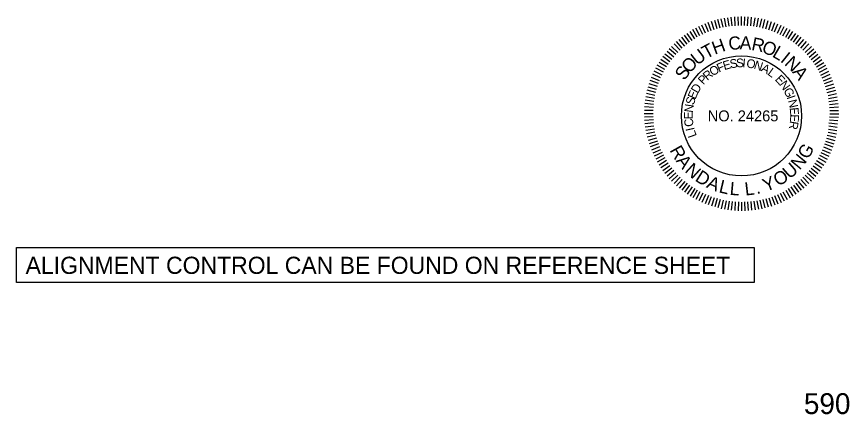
# Model space of a CAD drawing. Extents: x 1964850 to 1967424, y 1116563 to 1122204.
# Drawn here: x 1967082.7 to 1967421.9, y 1119325.5 to 1119487.7 of the extents above; entities that cross this region are included whole.
import ezdxf

# ---------------------------------------------------------------- set-up
doc = ezdxf.new("R2010")
doc.units = 0
for name, color, linetype in [('RD_DDB_Profile_Elev', 7, 'Continuous'), ('RD_Sketch1', 7, 'Continuous'), ('RD_TX_PEShield', 7, 'Continuous')]:
    doc.layers.add(name, color=color, linetype=linetype)

msp = doc.modelspace()

# ---------------------------------------------------------------- linework, layer by layer
at = {"layer": 'RD_Sketch1'}
msp.add_lwpolyline([(1967082.71, 1119393.46), (1967383.14, 1119393.46), (1967383.14, 1119379.2), (1967082.71, 1119379.2)], close=True, dxfattribs=at)
at = {"layer": 'RD_TX_PEShield'}
for p, q in [((1967364.52, 1119481.44), (1967363.18, 1119484.74)), ((1967364.52, 1119481.44), (1967363.18, 1119484.74)), ((1967365.69, 1119481.89), (1967364.47, 1119485.23)), ((1967365.69, 1119481.89), (1967364.47, 1119485.23)), ((1967366.86, 1119482.34), (1967365.76, 1119485.73)), ((1967366.86, 1119482.34), (1967365.76, 1119485.73)), ((1967368.08, 1119482.67), (1967367.1, 1119486.08)), ((1967368.08, 1119482.67), (1967367.1, 1119486.08)), ((1967369.29, 1119482.99), (1967368.43, 1119486.44)), ((1967369.29, 1119482.99), (1967368.43, 1119486.44)), ((1967370.51, 1119483.32), (1967369.77, 1119486.8)), ((1967370.51, 1119483.32), (1967369.77, 1119486.8)), ((1967371.75, 1119483.51), (1967371.13, 1119487.02)), ((1967371.75, 1119483.51), (1967371.13, 1119487.02)), ((1967372.99, 1119483.71), (1967372.5, 1119487.23)), ((1967372.99, 1119483.71), (1967372.5, 1119487.23)), ((1967374.24, 1119483.91), (1967373.86, 1119487.45)), ((1967374.24, 1119483.91), (1967373.86, 1119487.45)), ((1967375.49, 1119483.97), (1967375.24, 1119487.52)), ((1967375.49, 1119483.97), (1967375.24, 1119487.52)), ((1967376.75, 1119484.04), (1967376.62, 1119487.59)), ((1967376.75, 1119484.04), (1967376.62, 1119487.59)), ((1967378, 1119484.1), (1967378, 1119487.66)), ((1967378, 1119484.1), (1967378, 1119487.66)), ((1967379.26, 1119484.04), (1967379.38, 1119487.59)), ((1967379.26, 1119484.04), (1967379.38, 1119487.59)), ((1967380.51, 1119483.97), (1967380.76, 1119487.52)), ((1967380.51, 1119483.97), (1967380.76, 1119487.52)), ((1967381.77, 1119483.91), (1967382.14, 1119487.45)), ((1967381.77, 1119483.91), (1967382.14, 1119487.45)), ((1967383.01, 1119483.71), (1967383.51, 1119487.23)), ((1967383.01, 1119483.71), (1967383.51, 1119487.23)), ((1967384.25, 1119483.51), (1967384.87, 1119487.02)), ((1967384.25, 1119483.51), (1967384.87, 1119487.02)), ((1967385.5, 1119483.32), (1967386.24, 1119486.8)), ((1967385.5, 1119483.32), (1967386.24, 1119486.8)), ((1967385.5, 1119483.32), (1967386.24, 1119486.8)), ((1967386.71, 1119482.99), (1967387.57, 1119486.44)), ((1967386.71, 1119482.99), (1967387.57, 1119486.44)), ((1967386.71, 1119482.99), (1967387.57, 1119486.44)), ((1967387.93, 1119482.67), (1967388.91, 1119486.08)), ((1967387.93, 1119482.67), (1967388.91, 1119486.08)), ((1967387.93, 1119482.67), (1967388.91, 1119486.08)), ((1967389.14, 1119482.34), (1967390.24, 1119485.73)), ((1967389.14, 1119482.34), (1967390.24, 1119485.73)), ((1967389.14, 1119482.34), (1967390.24, 1119485.73)), ((1967390.32, 1119481.89), (1967391.53, 1119485.23)), ((1967390.32, 1119481.89), (1967391.53, 1119485.23)), ((1967390.32, 1119481.89), (1967391.53, 1119485.23)), ((1967391.49, 1119481.44), (1967392.82, 1119484.74)), ((1967391.49, 1119481.44), (1967392.82, 1119484.74)), ((1967391.49, 1119481.44), (1967392.82, 1119484.74)), ((1967358.93, 1119478.59), (1967357.04, 1119481.61)), ((1967358.93, 1119478.59), (1967357.04, 1119481.61)), ((1967359.98, 1119479.28), (1967358.2, 1119482.36)), ((1967359.98, 1119479.28), (1967358.2, 1119482.36)), ((1967361.1, 1119479.85), (1967359.43, 1119482.99)), ((1967361.1, 1119479.85), (1967359.43, 1119482.99)), ((1967362.22, 1119480.42), (1967360.66, 1119483.61)), ((1967362.22, 1119480.42), (1967360.66, 1119483.61)), ((1967363.34, 1119480.99), (1967361.89, 1119484.24)), ((1967363.34, 1119480.99), (1967361.89, 1119484.24)), ((1967392.66, 1119480.99), (1967394.11, 1119484.24)), ((1967392.66, 1119480.99), (1967394.11, 1119484.24)), ((1967392.66, 1119480.99), (1967394.11, 1119484.24)), ((1967393.79, 1119480.42), (1967395.34, 1119483.61)), ((1967393.79, 1119480.42), (1967395.34, 1119483.61)), ((1967393.79, 1119480.42), (1967395.34, 1119483.61)), ((1967394.9, 1119479.85), (1967396.57, 1119482.99)), ((1967394.9, 1119479.85), (1967396.57, 1119482.99)), ((1967394.9, 1119479.85), (1967396.57, 1119482.99)), ((1967396.03, 1119479.28), (1967397.81, 1119482.36)), ((1967396.03, 1119479.28), (1967397.81, 1119482.36)), ((1967396.03, 1119479.28), (1967397.81, 1119482.36)), ((1967397.08, 1119478.59), (1967398.97, 1119481.61)), ((1967397.08, 1119478.59), (1967398.97, 1119481.61)), ((1967397.08, 1119478.59), (1967398.97, 1119481.61)), ((1967354.86, 1119475.64), (1967352.58, 1119478.36)), ((1967354.86, 1119475.64), (1967352.58, 1119478.36)), ((1967355.84, 1119476.43), (1967353.65, 1119479.23)), ((1967355.84, 1119476.43), (1967353.65, 1119479.23)), ((1967356.82, 1119477.22), (1967354.72, 1119480.1)), ((1967356.82, 1119477.22), (1967354.72, 1119480.1)), ((1967357.87, 1119477.91), (1967355.88, 1119480.85)), ((1967357.87, 1119477.91), (1967355.88, 1119480.85)), ((1967398.13, 1119477.91), (1967400.12, 1119480.85)), ((1967398.13, 1119477.91), (1967400.12, 1119480.85)), ((1967398.13, 1119477.91), (1967400.12, 1119480.85)), ((1967399.19, 1119477.22), (1967401.28, 1119480.1)), ((1967399.19, 1119477.22), (1967401.28, 1119480.1)), ((1967399.19, 1119477.22), (1967401.28, 1119480.1)), ((1967400.17, 1119476.43), (1967402.36, 1119479.23)), ((1967400.17, 1119476.43), (1967402.36, 1119479.23)), ((1967400.17, 1119476.43), (1967402.36, 1119479.23)), ((1967401.14, 1119475.64), (1967403.43, 1119478.36)), ((1967401.14, 1119475.64), (1967403.43, 1119478.36)), ((1967401.14, 1119475.64), (1967403.43, 1119478.36)), ((1967351.22, 1119472.18), (1967348.57, 1119474.56)), ((1967351.22, 1119472.18), (1967348.57, 1119474.56)), ((1967352.11, 1119473.07), (1967349.55, 1119475.54)), ((1967352.11, 1119473.07), (1967349.55, 1119475.54)), ((1967352.99, 1119473.96), (1967350.52, 1119476.51)), ((1967352.99, 1119473.96), (1967350.52, 1119476.51)), ((1967353.88, 1119474.85), (1967351.5, 1119477.49)), ((1967353.88, 1119474.85), (1967351.5, 1119477.49)), ((1967402.12, 1119474.85), (1967404.5, 1119477.49)), ((1967402.12, 1119474.85), (1967404.5, 1119477.49)), ((1967402.12, 1119474.85), (1967404.5, 1119477.49)), ((1967403.01, 1119473.96), (1967405.48, 1119476.51)), ((1967403.01, 1119473.96), (1967405.48, 1119476.51)), ((1967403.01, 1119473.96), (1967405.48, 1119476.51)), ((1967403.9, 1119473.07), (1967406.46, 1119475.54)), ((1967403.9, 1119473.07), (1967406.46, 1119475.54)), ((1967403.9, 1119473.07), (1967406.46, 1119475.54)), ((1967404.79, 1119472.18), (1967407.44, 1119474.56)), ((1967404.79, 1119472.18), (1967407.44, 1119474.56)), ((1967404.79, 1119472.18), (1967407.44, 1119474.56)), ((1967348.84, 1119469.25), (1967345.96, 1119471.34)), ((1967348.84, 1119469.25), (1967345.96, 1119471.34)), ((1967349.63, 1119470.22), (1967346.83, 1119472.41)), ((1967349.63, 1119470.22), (1967346.83, 1119472.41)), ((1967350.42, 1119471.2), (1967347.7, 1119473.49)), ((1967350.42, 1119471.2), (1967347.7, 1119473.49)), ((1967405.58, 1119471.2), (1967408.31, 1119473.49)), ((1967405.58, 1119471.2), (1967408.31, 1119473.49)), ((1967405.58, 1119471.2), (1967408.31, 1119473.49)), ((1967406.37, 1119470.22), (1967409.17, 1119472.41)), ((1967406.37, 1119470.22), (1967409.17, 1119472.41)), ((1967406.37, 1119470.22), (1967409.17, 1119472.41)), ((1967407.16, 1119469.25), (1967410.04, 1119471.34)), ((1967407.16, 1119469.25), (1967410.04, 1119471.34)), ((1967407.16, 1119469.25), (1967410.04, 1119471.34)), ((1967346.79, 1119466.08), (1967343.7, 1119467.86)), ((1967346.79, 1119466.08), (1967343.7, 1119467.86)), ((1967347.47, 1119467.14), (1967344.46, 1119469.02)), ((1967347.47, 1119467.14), (1967344.46, 1119469.02)), ((1967348.16, 1119468.19), (1967345.21, 1119470.18)), ((1967348.16, 1119468.19), (1967345.21, 1119470.18)), ((1967407.85, 1119468.19), (1967410.8, 1119470.18)), ((1967407.85, 1119468.19), (1967410.8, 1119470.18)), ((1967407.85, 1119468.19), (1967410.8, 1119470.18)), ((1967408.53, 1119467.14), (1967411.55, 1119469.02)), ((1967408.53, 1119467.14), (1967411.55, 1119469.02)), ((1967408.53, 1119467.14), (1967411.55, 1119469.02)), ((1967409.22, 1119466.08), (1967412.3, 1119467.86)), ((1967409.22, 1119466.08), (1967412.3, 1119467.86)), ((1967409.22, 1119466.08), (1967412.3, 1119467.86)), ((1967345.65, 1119463.84), (1967342.45, 1119465.4)), ((1967345.65, 1119463.84), (1967342.45, 1119465.4)), ((1967346.22, 1119464.96), (1967343.08, 1119466.63)), ((1967346.22, 1119464.96), (1967343.08, 1119466.63)), ((1967409.79, 1119464.96), (1967412.93, 1119466.63)), ((1967409.79, 1119464.96), (1967412.93, 1119466.63)), ((1967409.79, 1119464.96), (1967412.93, 1119466.63)), ((1967410.36, 1119463.84), (1967413.56, 1119465.4)), ((1967410.36, 1119463.84), (1967413.56, 1119465.4)), ((1967410.36, 1119463.84), (1967413.56, 1119465.4)), ((1967344.17, 1119460.37), (1967340.83, 1119461.59)), ((1967344.17, 1119460.37), (1967340.83, 1119461.59)), ((1967344.62, 1119461.55), (1967341.33, 1119462.88)), ((1967344.62, 1119461.55), (1967341.33, 1119462.88)), ((1967345.07, 1119462.72), (1967341.82, 1119464.17)), ((1967345.07, 1119462.72), (1967341.82, 1119464.17)), ((1967410.93, 1119462.72), (1967414.18, 1119464.17)), ((1967410.93, 1119462.72), (1967414.18, 1119464.17)), ((1967410.93, 1119462.72), (1967414.18, 1119464.17)), ((1967411.38, 1119461.55), (1967414.68, 1119462.88)), ((1967411.38, 1119461.55), (1967414.68, 1119462.88)), ((1967411.38, 1119461.55), (1967414.68, 1119462.88)), ((1967411.83, 1119460.37), (1967415.17, 1119461.59)), ((1967411.83, 1119460.37), (1967415.17, 1119461.59)), ((1967411.83, 1119460.37), (1967415.17, 1119461.59)), ((1967343.07, 1119456.77), (1967339.62, 1119457.63)), ((1967343.07, 1119456.77), (1967339.62, 1119457.63)), ((1967343.4, 1119457.98), (1967339.98, 1119458.96)), ((1967343.4, 1119457.98), (1967339.98, 1119458.96)), ((1967343.72, 1119459.2), (1967340.34, 1119460.3)), ((1967343.72, 1119459.2), (1967340.34, 1119460.3)), ((1967412.28, 1119459.2), (1967415.67, 1119460.3)), ((1967412.28, 1119459.2), (1967415.67, 1119460.3)), ((1967412.28, 1119459.2), (1967415.67, 1119460.3)), ((1967412.61, 1119457.98), (1967416.03, 1119458.96)), ((1967412.61, 1119457.98), (1967416.03, 1119458.96)), ((1967412.61, 1119457.98), (1967416.03, 1119458.96)), ((1967412.93, 1119456.77), (1967416.38, 1119457.63)), ((1967412.93, 1119456.77), (1967416.38, 1119457.63)), ((1967412.93, 1119456.77), (1967416.38, 1119457.63)), ((1967342.55, 1119454.31), (1967339.05, 1119454.93)), ((1967342.55, 1119454.31), (1967339.05, 1119454.93)), ((1967342.75, 1119455.55), (1967339.26, 1119456.29)), ((1967342.75, 1119455.55), (1967339.26, 1119456.29)), ((1967413.26, 1119455.55), (1967416.74, 1119456.29)), ((1967413.26, 1119455.55), (1967416.74, 1119456.29)), ((1967413.26, 1119455.55), (1967416.74, 1119456.29)), ((1967413.46, 1119454.31), (1967416.96, 1119454.93)), ((1967413.46, 1119454.31), (1967416.96, 1119454.93)), ((1967413.46, 1119454.31), (1967416.96, 1119454.93)), ((1967342.09, 1119450.57), (1967338.54, 1119450.82)), ((1967342.09, 1119450.57), (1967338.54, 1119450.82)), ((1967342.16, 1119451.83), (1967338.62, 1119452.2)), ((1967342.16, 1119451.83), (1967338.62, 1119452.2)), ((1967342.35, 1119453.07), (1967338.83, 1119453.56)), ((1967342.35, 1119453.07), (1967338.83, 1119453.56)), ((1967413.65, 1119453.07), (1967417.17, 1119453.56)), ((1967413.65, 1119453.07), (1967417.17, 1119453.56)), ((1967413.65, 1119453.07), (1967417.17, 1119453.56)), ((1967413.85, 1119451.83), (1967417.39, 1119452.2)), ((1967413.85, 1119451.83), (1967417.39, 1119452.2)), ((1967413.85, 1119451.83), (1967417.39, 1119452.2)), ((1967413.92, 1119450.57), (1967417.46, 1119450.82)), ((1967413.92, 1119450.57), (1967417.46, 1119450.82)), ((1967413.92, 1119450.57), (1967417.46, 1119450.82)), ((1967341.96, 1119448.06), (1967338.4, 1119448.06)), ((1967341.96, 1119448.06), (1967338.4, 1119448.06)), ((1967342.02, 1119449.32), (1967338.47, 1119449.44)), ((1967342.02, 1119449.32), (1967338.47, 1119449.44)), ((1967413.98, 1119449.32), (1967417.54, 1119449.44)), ((1967413.98, 1119449.32), (1967417.54, 1119449.44)), ((1967413.98, 1119449.32), (1967417.54, 1119449.44)), ((1967414.05, 1119448.06), (1967417.61, 1119448.06)), ((1967414.05, 1119448.06), (1967417.61, 1119448.06)), ((1967414.05, 1119448.06), (1967417.61, 1119448.06)), ((1967342.02, 1119446.8), (1967338.47, 1119446.68)), ((1967342.02, 1119446.8), (1967338.47, 1119446.68)), ((1967342.09, 1119445.55), (1967338.54, 1119445.3)), ((1967342.09, 1119445.55), (1967338.54, 1119445.3)), ((1967342.16, 1119444.29), (1967338.62, 1119443.92)), ((1967342.16, 1119444.29), (1967338.62, 1119443.92)), ((1967413.65, 1119444.31), (1967417.18, 1119443.94)), ((1967413.65, 1119444.31), (1967417.18, 1119443.94)), ((1967413.79, 1119445.56), (1967417.32, 1119445.31)), ((1967413.79, 1119445.56), (1967417.32, 1119445.31)), ((1967413.92, 1119446.81), (1967417.46, 1119446.68)), ((1967413.92, 1119446.81), (1967417.46, 1119446.68)), ((1967342.35, 1119443.05), (1967338.83, 1119442.55)), ((1967342.35, 1119443.05), (1967338.83, 1119442.55)), ((1967342.55, 1119441.81), (1967339.05, 1119441.19)), ((1967342.55, 1119441.81), (1967339.05, 1119441.19)), ((1967342.75, 1119440.57), (1967339.26, 1119439.83)), ((1967342.75, 1119440.57), (1967339.26, 1119439.83)), ((1967413.26, 1119440.57), (1967416.74, 1119439.83)), ((1967413.26, 1119440.57), (1967416.74, 1119439.83)), ((1967413.39, 1119441.82), (1967416.89, 1119441.2)), ((1967413.39, 1119441.82), (1967416.89, 1119441.2)), ((1967413.52, 1119443.07), (1967417.03, 1119442.57)), ((1967413.52, 1119443.07), (1967417.03, 1119442.57)), ((1967343.07, 1119439.35), (1967339.62, 1119438.49)), ((1967343.07, 1119439.35), (1967339.62, 1119438.49)), ((1967343.4, 1119438.14), (1967339.98, 1119437.16)), ((1967343.4, 1119438.14), (1967339.98, 1119437.16)), ((1967412.61, 1119438.14), (1967416.03, 1119437.16)), ((1967412.61, 1119438.14), (1967416.03, 1119437.16)), ((1967412.93, 1119439.35), (1967416.38, 1119438.49)), ((1967412.93, 1119439.35), (1967416.38, 1119438.49)), ((1967343.72, 1119436.92), (1967340.34, 1119435.82)), ((1967344.17, 1119435.75), (1967340.83, 1119434.53)), ((1967344.17, 1119435.75), (1967340.83, 1119434.53)), ((1967344.62, 1119434.57), (1967341.33, 1119433.24)), ((1967344.62, 1119434.57), (1967341.33, 1119433.24)), ((1967411.38, 1119434.57), (1967414.68, 1119433.24)), ((1967411.38, 1119434.57), (1967414.68, 1119433.24)), ((1967411.83, 1119435.75), (1967415.17, 1119434.53)), ((1967411.83, 1119435.75), (1967415.17, 1119434.53)), ((1967412.28, 1119436.92), (1967415.67, 1119435.82)), ((1967412.28, 1119436.92), (1967415.67, 1119435.82)), ((1967345.07, 1119433.4), (1967341.82, 1119431.95)), ((1967345.07, 1119433.4), (1967341.82, 1119431.95)), ((1967345.65, 1119432.28), (1967342.45, 1119430.72)), ((1967345.65, 1119432.28), (1967342.45, 1119430.72)), ((1967346.22, 1119431.16), (1967343.08, 1119429.49)), ((1967346.22, 1119431.16), (1967343.08, 1119429.49)), ((1967409.79, 1119431.16), (1967412.93, 1119429.49)), ((1967409.79, 1119431.16), (1967412.93, 1119429.49)), ((1967410.36, 1119432.28), (1967413.56, 1119430.72)), ((1967410.36, 1119432.28), (1967413.56, 1119430.72)), ((1967410.93, 1119433.4), (1967414.18, 1119431.95)), ((1967410.93, 1119433.4), (1967414.18, 1119431.95)), ((1967346.79, 1119430.04), (1967343.7, 1119428.26)), ((1967346.79, 1119430.04), (1967343.7, 1119428.26)), ((1967347.47, 1119428.98), (1967344.46, 1119427.1)), ((1967347.47, 1119428.98), (1967344.46, 1119427.1)), ((1967348.16, 1119427.93), (1967345.21, 1119425.94)), ((1967348.16, 1119427.93), (1967345.21, 1119425.94)), ((1967407.85, 1119427.93), (1967410.8, 1119425.94)), ((1967407.85, 1119427.93), (1967410.8, 1119425.94)), ((1967408.53, 1119428.98), (1967411.55, 1119427.1)), ((1967408.53, 1119428.98), (1967411.55, 1119427.1)), ((1967409.22, 1119430.04), (1967412.3, 1119428.26)), ((1967409.22, 1119430.04), (1967412.3, 1119428.26)), ((1967348.84, 1119426.87), (1967345.96, 1119424.78)), ((1967348.84, 1119426.87), (1967345.96, 1119424.78)), ((1967349.63, 1119425.89), (1967346.83, 1119423.71)), ((1967349.63, 1119425.89), (1967346.83, 1119423.71)), ((1967350.42, 1119424.92), (1967347.7, 1119422.63)), ((1967350.42, 1119424.92), (1967347.7, 1119422.63)), ((1967351.22, 1119423.94), (1967348.57, 1119421.56)), ((1967351.22, 1119423.94), (1967348.57, 1119421.56)), ((1967404.79, 1119423.94), (1967407.44, 1119421.56)), ((1967404.79, 1119423.94), (1967407.44, 1119421.56)), ((1967405.58, 1119424.92), (1967408.31, 1119422.63)), ((1967405.58, 1119424.92), (1967408.31, 1119422.63)), ((1967406.37, 1119425.89), (1967409.17, 1119423.71)), ((1967406.37, 1119425.89), (1967409.17, 1119423.71)), ((1967407.16, 1119426.87), (1967410.04, 1119424.78)), ((1967407.16, 1119426.87), (1967410.04, 1119424.78)), ((1967352.11, 1119423.05), (1967349.55, 1119420.58)), ((1967352.11, 1119423.05), (1967349.55, 1119420.58)), ((1967352.99, 1119422.16), (1967350.52, 1119419.6)), ((1967352.99, 1119422.16), (1967350.52, 1119419.6)), ((1967353.88, 1119421.27), (1967351.5, 1119418.63)), ((1967353.88, 1119421.27), (1967351.5, 1119418.63)), ((1967354.86, 1119420.48), (1967352.58, 1119417.76)), ((1967354.86, 1119420.48), (1967352.58, 1119417.76)), ((1967401.14, 1119420.48), (1967403.43, 1119417.76)), ((1967401.14, 1119420.48), (1967403.43, 1119417.76)), ((1967402.12, 1119421.27), (1967404.5, 1119418.63)), ((1967403.01, 1119422.16), (1967405.48, 1119419.6)), ((1967403.01, 1119422.16), (1967405.48, 1119419.6)), ((1967403.9, 1119423.05), (1967406.46, 1119420.58)), ((1967403.9, 1119423.05), (1967406.46, 1119420.58)), ((1967355.84, 1119419.69), (1967353.65, 1119416.89)), ((1967355.84, 1119419.69), (1967353.65, 1119416.89)), ((1967356.82, 1119418.9), (1967354.72, 1119416.02)), ((1967356.82, 1119418.9), (1967354.72, 1119416.02)), ((1967357.87, 1119418.21), (1967355.88, 1119415.27)), ((1967357.87, 1119418.21), (1967355.88, 1119415.27)), ((1967358.93, 1119417.53), (1967357.04, 1119414.51)), ((1967358.93, 1119417.53), (1967357.04, 1119414.51)), ((1967359.98, 1119416.84), (1967358.2, 1119413.76)), ((1967359.98, 1119416.84), (1967358.2, 1119413.76)), ((1967396.03, 1119416.84), (1967397.81, 1119413.76)), ((1967396.03, 1119416.84), (1967397.81, 1119413.76)), ((1967397.08, 1119417.53), (1967398.97, 1119414.51)), ((1967397.08, 1119417.53), (1967398.97, 1119414.51)), ((1967398.13, 1119418.21), (1967400.12, 1119415.27)), ((1967398.13, 1119418.21), (1967400.12, 1119415.27)), ((1967399.19, 1119418.9), (1967401.28, 1119416.02)), ((1967399.19, 1119418.9), (1967401.28, 1119416.02)), ((1967400.17, 1119419.69), (1967402.36, 1119416.89)), ((1967400.17, 1119419.69), (1967402.36, 1119416.89)), ((1967361.1, 1119416.27), (1967359.43, 1119413.13)), ((1967361.1, 1119416.27), (1967359.43, 1119413.13)), ((1967362.22, 1119415.7), (1967360.66, 1119412.51)), ((1967362.22, 1119415.7), (1967360.66, 1119412.51)), ((1967363.34, 1119415.13), (1967361.89, 1119411.88)), ((1967363.34, 1119415.13), (1967361.89, 1119411.88)), ((1967364.52, 1119414.68), (1967363.18, 1119411.38)), ((1967364.52, 1119414.68), (1967363.18, 1119411.38)), ((1967365.69, 1119414.23), (1967364.47, 1119410.89)), ((1967365.69, 1119414.23), (1967364.47, 1119410.89)), ((1967366.86, 1119413.78), (1967365.76, 1119410.39)), ((1967366.86, 1119413.78), (1967365.76, 1119410.39)), ((1967368.08, 1119413.45), (1967367.1, 1119410.03)), ((1967368.08, 1119413.45), (1967367.1, 1119410.03)), ((1967387.93, 1119413.45), (1967388.91, 1119410.03)), ((1967387.93, 1119413.45), (1967388.91, 1119410.03)), ((1967389.14, 1119413.78), (1967390.24, 1119410.39)), ((1967389.14, 1119413.78), (1967390.24, 1119410.39)), ((1967390.32, 1119414.23), (1967391.53, 1119410.89)), ((1967390.32, 1119414.23), (1967391.53, 1119410.89)), ((1967391.49, 1119414.68), (1967392.82, 1119411.38)), ((1967391.49, 1119414.68), (1967392.82, 1119411.38)), ((1967392.66, 1119415.13), (1967394.11, 1119411.88)), ((1967392.66, 1119415.13), (1967394.11, 1119411.88)), ((1967393.79, 1119415.7), (1967395.34, 1119412.51)), ((1967393.79, 1119415.7), (1967395.34, 1119412.51)), ((1967394.9, 1119416.27), (1967396.57, 1119413.13)), ((1967394.9, 1119416.27), (1967396.57, 1119413.13)), ((1967369.29, 1119413.13), (1967368.43, 1119409.68)), ((1967369.29, 1119413.13), (1967368.43, 1119409.68)), ((1967370.51, 1119412.8), (1967369.77, 1119409.32)), ((1967370.51, 1119412.8), (1967369.77, 1119409.32)), ((1967371.75, 1119412.61), (1967371.13, 1119409.1)), ((1967371.75, 1119412.61), (1967371.13, 1119409.1)), ((1967372.99, 1119412.41), (1967372.5, 1119408.89)), ((1967372.99, 1119412.41), (1967372.5, 1119408.89)), ((1967374.24, 1119412.21), (1967373.86, 1119408.67)), ((1967374.24, 1119412.21), (1967373.86, 1119408.67)), ((1967375.49, 1119412.15), (1967375.24, 1119408.6)), ((1967375.49, 1119412.15), (1967375.24, 1119408.6)), ((1967376.75, 1119412.08), (1967376.62, 1119408.53)), ((1967376.75, 1119412.08), (1967376.62, 1119408.53)), ((1967378, 1119412.01), (1967378, 1119408.45)), ((1967378, 1119412.01), (1967378, 1119408.45)), ((1967379.26, 1119412.08), (1967379.38, 1119408.53)), ((1967379.26, 1119412.08), (1967379.38, 1119408.53)), ((1967380.51, 1119412.15), (1967380.76, 1119408.6)), ((1967380.51, 1119412.15), (1967380.76, 1119408.6)), ((1967381.77, 1119412.21), (1967382.14, 1119408.67)), ((1967381.77, 1119412.21), (1967382.14, 1119408.67)), ((1967383.01, 1119412.41), (1967383.51, 1119408.89)), ((1967383.01, 1119412.41), (1967383.51, 1119408.89)), ((1967384.25, 1119412.61), (1967384.87, 1119409.1)), ((1967384.25, 1119412.61), (1967384.87, 1119409.1)), ((1967385.5, 1119412.8), (1967386.24, 1119409.32)), ((1967385.5, 1119412.8), (1967386.24, 1119409.32)), ((1967386.71, 1119413.13), (1967387.57, 1119409.68)), ((1967386.71, 1119413.13), (1967387.57, 1119409.68))]:
    msp.add_line(p, q, dxfattribs=at)
msp.add_circle((1967378, 1119447.18), 24.48, dxfattribs=at)

# ---------------------------------------------------------------- texts
at = {"layer": 'RD_DDB_Profile_Elev'}
msp.add_text('590', height=8.5, dxfattribs=at).set_placement((1967403.42, 1119325.58))
at = {"layer": 'RD_Sketch1'}
msp.add_text('ALIGNMENT CONTROL CAN BE FOUND ON REFERENCE SHEET', height=7, dxfattribs=at).set_placement((1967086.36, 1119382.75))
at = {"layer": 'RD_TX_PEShield'}
for s, height, rotation, p in [('H', 5.34, 19.9102, (1967367.1, 1119472.1)), ('C', 5.34, 6.8832, (1967373, 1119473.92)), ('A', 5.34, 357.9448, (1967377.21, 1119474.37)), ('R', 5.34, 348.267, (1967381.79, 1119474.12)), ('U', 5.34, 37.7726, (1967359.98, 1119467.56)), ('T', 5.34, 28.0947, (1967363.66, 1119470.3)), ('O', 5.34, 339.3286, (1967385.93, 1119473.2)), ('L', 5.34, 329.6507, (1967390.2, 1119471.5)), ('I', 5.34, 321.4663, (1967393.53, 1119469.51)), ('N', 5.34, 317.0007, (1967395.22, 1119468.24)), ('O', 5.34, 47.4504, (1967356.81, 1119464.24)), ('F', 3.56, 23.0853, (1967368.81, 1119464.84)), ('E', 3.56, 16.1843, (1967371, 1119465.82)), ('S', 3.56, 8.6909, (1967373.49, 1119466.57)), ('S', 3.56, 1.79, (1967375.85, 1119466.97)), ('I', 3.56, 354.889, (1967378.25, 1119467.09)), ('O', 3.56, 350.4045, (1967379.8, 1119467.01)), ('N', 3.56, 341.7029, (1967382.78, 1119466.51)), ('A', 3.56, 333.0013, (1967385.65, 1119465.56)), ('S', 5.34, 54.9027, (1967354.78, 1119461.34)), ('R', 3.56, 39.8902, (1967364.1, 1119461.43)), ('O', 3.56, 31.7869, (1967366.25, 1119463.25)), ('L', 3.56, 324.2997, (1967388.34, 1119464.19)), ('A', 5.34, 307.3229, (1967398.52, 1119465.04)), ('P', 3.56, 46.7912, (1967362.49, 1119459.65)), ('E', 3.56, 313.2251, (1967391.42, 1119461.89)), ('N', 3.56, 305.7317, (1967393.22, 1119460.01)), ('E', 3.56, 66.5674, (1967359.18, 1119453.67)), ('D', 3.56, 59.074, (1967360.19, 1119456.07)), ('G', 3.56, 297.0301, (1967394.99, 1119457.56)), ('S', 3.56, 73.4683, (1967358.54, 1119451.36)), ('I', 3.56, 288.3285, (1967396.36, 1119454.88)), ('N', 3.56, 82.17, (1967358.13, 1119448.37)), ('N', 3.56, 283.8441, (1967396.91, 1119453.42)), ('E', 3.56, 89.6633, (1967358.15, 1119445.77)), ('E', 3.56, 275.1424, (1967397.63, 1119450.48)), ('E', 3.56, 267.6491, (1967397.9, 1119447.9)), ('C', 3.56, 97.7667, (1967358.54, 1119442.98)), ('R', 3.56, 260.1557, (1967397.82, 1119445.3)), ('I', 3.56, 102.2511, (1967358.93, 1119441.47)), ('L', 3.56, 109.7445, (1967359.84, 1119439.04)), ('R', 5.34, 299.1493, (1967348.6, 1119433.21)), ('G', 5.34, 60.1113, (1967405.11, 1119429.16)), ('A', 5.34, 308.0877, (1967351.13, 1119428.81)), ('N', 5.34, 50.4335, (1967401.7, 1119424.86)), ('N', 5.34, 317.7655, (1967354.6, 1119424.55)), ('U', 5.34, 40.7556, (1967397.61, 1119421.19)), ('D', 5.34, 327.4433, (1967358.74, 1119420.94)), ('O', 5.34, 31.0778, (1967392.96, 1119418.27)), ('A', 5.34, 337.1212, (1967363.42, 1119418.08)), ('L', 5.34, 346.799, (1967368.52, 1119416.04)), ('L', 5.34, 354.9835, (1967373.05, 1119415.01)), ('Y', 5.34, 21.4, (1967387.88, 1119416.16)), ('L', 5.34, 6.5171, (1967379.59, 1119414.67)), ('.', 5.34, 14.7016, (1967384.2, 1119415.22))]:
    msp.add_text(s, height=height, rotation=rotation, dxfattribs=at).set_placement(p)
msp.add_text('NO. 24265', height=4.45, dxfattribs=at).set_placement((1967364.25, 1119444.96))

doc.saveas('drawing.dxf')
